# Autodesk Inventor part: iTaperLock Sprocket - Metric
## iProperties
Author: scotta
Shininess: 64.0
Angle Display Precision: 2
Document Length Units: 11269
Document Angle Units: 11283
Document Time Units: 11279
Document Mass Units: 11290
Document Length Units Precision: 3
Document Angle Units Precision: 2
Compacted: True
PropertySet Name: _Private Model Information
Created: 2002-04
Part Number: iTaperLock Sprocket - Metric
Material: Steel, Mild
Document SubType Name: Modeling
Designer: scotta
Control State: 0
Master: False
Checked Out: False
PropertySet Name: Design Tracking Control
Density: 0.0
Volumn: 0.0
Area: 0.0
PropertySet Name: Model Information
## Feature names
1. Extrusion1
2. Sprocket Disc [Extrusion]
3. Sprocket Chamfer 1 [Chamfer]
4. Sprocket Chamfer 2 [Chamfer]
5. Tooth Cut [Extrusion]
6. Tooth Cut Array [Circular Pattern]
7. TaperBore [Extrusion]
8. ExtractionHole [Hole]
9. Hole2
